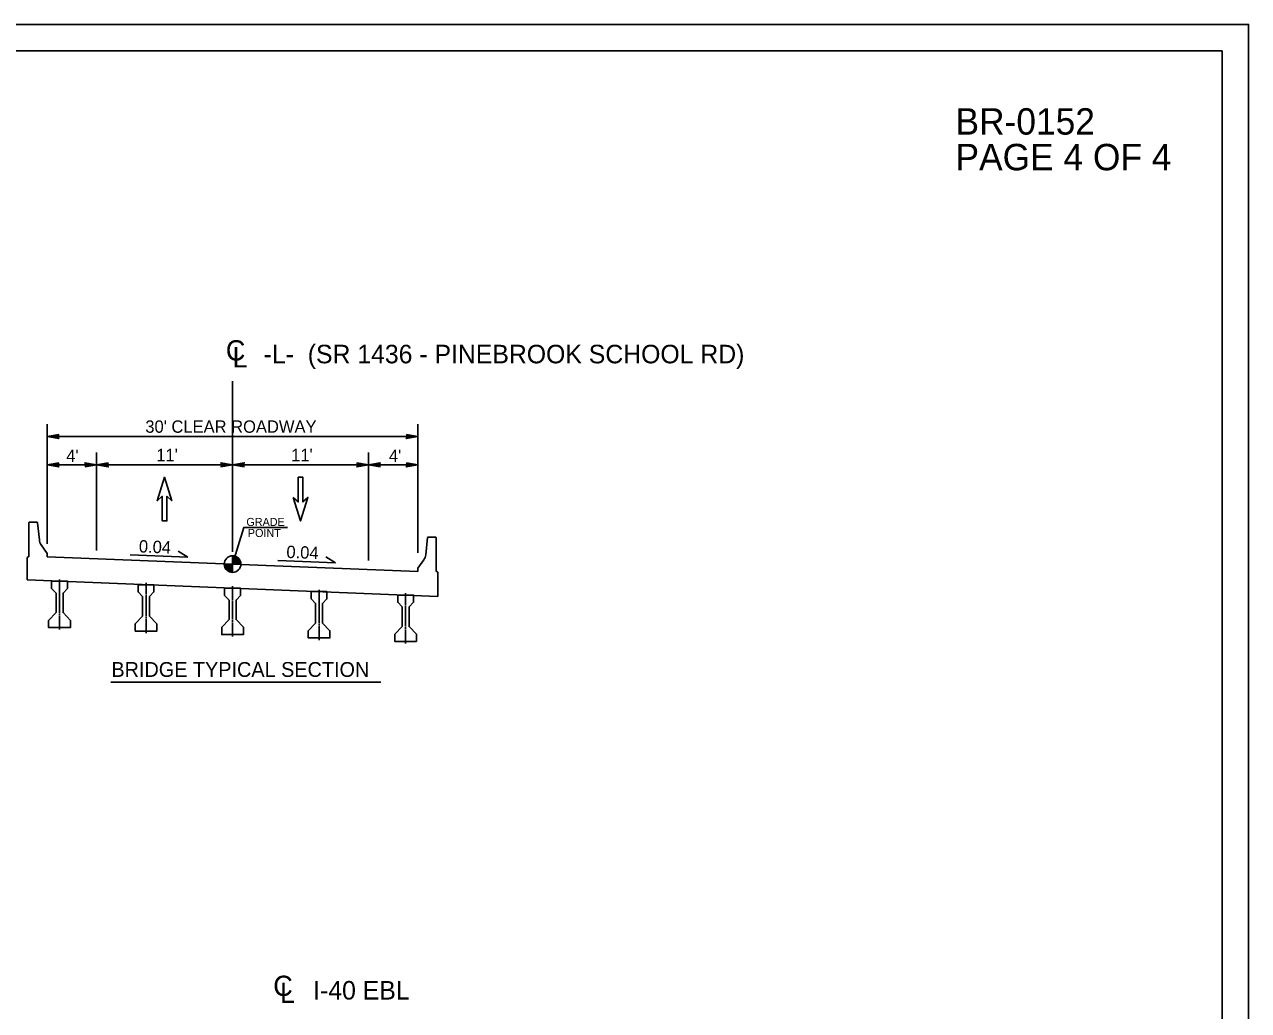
# Model space of a CAD drawing. Extents: x 1553195 to 1553792, y 810516 to 810787.
# Drawn here: x 1553567 to 1553666, y 810706.7 to 810786.5 of the extents above; entities that cross this region are included whole.
import ezdxf

# ---------------------------------------------------------------- set-up
doc = ezdxf.new("R2010")
doc.units = 0
for name, color, linetype in [('Old_Level_11', 7, 'Continuous'), ('Prop Dimension', 7, 'Continuous'), ('Prop Dimension Text', 7, 'Continuous'), ('Prop DSN Text', 7, 'Continuous'), ('Prop Pavement Schedule Description CELL', 7, 'Continuous'), ('Prop Shade Light', 7, 'Continuous'), ('Prop Terminator CELL', 7, 'Continuous'), ('Prop Typical Section', 7, 'Continuous'), ('Sheet Data Field CELL', 7, 'Continuous'), ('Sheet Plan CELL', 7, 'Continuous'), ('Typical Text ID Circle CELL', 7, 'Continuous'), ('z - Construction', 7, 'Continuous')]:
    doc.layers.add(name, color=color, linetype=linetype)

msp = doc.modelspace()

# ---------------------------------------------------------------- linework, layer by layer
at = {"layer": 'Old_Level_11'}
for p, q in [((1553583.839, 810742.867), (1553583.839, 810743.539)), ((1553583.168, 810742.867), (1553583.839, 810742.867)), ((1553583.838, 810742.196), (1553583.839, 810742.867)), ((1553583.839, 810742.867), (1553583.838, 810742.196)), ((1553584.511, 810742.867), (1553583.839, 810742.867))]:
    msp.add_line(p, q, dxfattribs=at)
for points in [[(1553583.845, 810743.539), (1553583.845, 810743.539), (1553583.845, 810742.867)], [(1553583.859, 810743.539), (1553583.859, 810742.867)], [(1553583.872, 810743.537), (1553583.872, 810742.867)], [(1553583.886, 810743.537), (1553583.886, 810742.867)], [(1553583.899, 810743.536), (1553583.899, 810742.867)], [(1553583.912, 810743.534), (1553583.912, 810742.867)], [(1553583.926, 810743.533), (1553583.926, 810742.867)], [(1553583.939, 810743.531), (1553583.939, 810742.867)], [(1553583.953, 810743.53), (1553583.953, 810742.867)], [(1553583.966, 810743.527), (1553583.966, 810742.867)], [(1553583.98, 810743.524), (1553583.98, 810742.867)], [(1553583.993, 810743.521), (1553583.993, 810742.867)], [(1553584.007, 810743.518), (1553584.007, 810742.867)], [(1553584.02, 810743.514), (1553584.02, 810742.867)], [(1553584.033, 810743.51), (1553584.033, 810742.867)], [(1553584.047, 810743.506), (1553584.047, 810742.867)], [(1553584.06, 810743.502), (1553584.06, 810742.867)], [(1553584.074, 810743.497), (1553584.074, 810742.867)], [(1553584.087, 810743.491), (1553584.087, 810742.867)], [(1553584.101, 810743.485), (1553584.101, 810742.867)], [(1553584.114, 810743.479), (1553584.114, 810742.867)], [(1553584.127, 810743.473), (1553584.127, 810742.867)], [(1553584.141, 810743.467), (1553584.141, 810742.867)], [(1553584.154, 810743.46), (1553584.154, 810742.867)], [(1553584.168, 810743.452), (1553584.168, 810742.867)], [(1553584.181, 810743.445), (1553584.181, 810742.867)], [(1553584.194, 810743.437), (1553584.194, 810742.867)], [(1553584.208, 810743.428), (1553584.208, 810742.867)], [(1553584.221, 810743.419), (1553584.221, 810742.867)], [(1553584.235, 810743.409), (1553584.235, 810742.867)], [(1553584.248, 810743.4), (1553584.248, 810742.867)], [(1553584.262, 810743.39), (1553584.262, 810742.867)], [(1553584.275, 810743.378), (1553584.275, 810742.867)], [(1553584.288, 810743.366), (1553584.288, 810742.867)], [(1553584.302, 810743.354), (1553584.302, 810742.867)], [(1553584.315, 810743.34), (1553584.315, 810742.867)], [(1553584.329, 810743.327), (1553584.329, 810742.867)], [(1553584.342, 810743.312), (1553584.342, 810742.867)], [(1553584.356, 810743.296), (1553584.356, 810742.867)], [(1553583.171, 810742.867), (1553583.171, 810742.794)], [(1553583.184, 810742.867), (1553583.184, 810742.715)], [(1553583.198, 810742.867), (1553583.198, 810742.668)], [(1553583.211, 810742.867), (1553583.211, 810742.627)], [(1553583.225, 810742.867), (1553583.225, 810742.596)], [(1553583.238, 810742.867), (1553583.238, 810742.568)], [(1553583.252, 810742.867), (1553583.252, 810742.542)], [(1553583.265, 810742.867), (1553583.265, 810742.518)], [(1553583.278, 810742.867), (1553583.278, 810742.498)], [(1553583.292, 810742.867), (1553583.292, 810742.478)], [(1553583.305, 810742.867), (1553583.305, 810742.46)], [(1553583.319, 810742.867), (1553583.319, 810742.444)], [(1553583.332, 810742.867), (1553583.332, 810742.427)], [(1553583.346, 810742.867), (1553583.346, 810742.412)], [(1553583.359, 810742.867), (1553583.359, 810742.398)], [(1553583.372, 810742.867), (1553583.372, 810742.384)], [(1553583.386, 810742.867), (1553583.386, 810742.372)], [(1553583.399, 810742.867), (1553583.399, 810742.36)], [(1553583.413, 810742.867), (1553583.413, 810742.348)], [(1553583.426, 810742.867), (1553583.426, 810742.338)], [(1553583.44, 810742.867), (1553583.44, 810742.327)], [(1553583.453, 810742.867), (1553583.453, 810742.318)], [(1553583.466, 810742.867), (1553583.466, 810742.309)], [(1553583.48, 810742.867), (1553583.48, 810742.301)], [(1553583.493, 810742.867), (1553583.493, 810742.292)], [(1553583.507, 810742.867), (1553583.507, 810742.284)], [(1553583.52, 810742.867), (1553583.52, 810742.277)], [(1553583.534, 810742.867), (1553583.534, 810742.269)], [(1553583.547, 810742.867), (1553583.547, 810742.263)], [(1553583.56, 810742.867), (1553583.56, 810742.257)], [(1553583.574, 810742.867), (1553583.574, 810742.251)], [(1553583.587, 810742.867), (1553583.587, 810742.245)], [(1553583.601, 810742.867), (1553583.601, 810742.239)], [(1553583.614, 810742.867), (1553583.614, 810742.235)], [(1553583.628, 810742.867), (1553583.628, 810742.23)], [(1553583.641, 810742.867), (1553583.641, 810742.226)], [(1553583.654, 810742.867), (1553583.654, 810742.223)], [(1553583.668, 810742.867), (1553583.668, 810742.218)], [(1553583.681, 810742.867), (1553583.681, 810742.216)], [(1553583.695, 810742.867), (1553583.695, 810742.212)], [(1553583.708, 810742.867), (1553583.708, 810742.21)], [(1553583.722, 810742.867), (1553583.722, 810742.207)], [(1553583.735, 810742.867), (1553583.735, 810742.205)], [(1553583.748, 810742.867), (1553583.748, 810742.202)], [(1553583.762, 810742.867), (1553583.762, 810742.201)], [(1553583.775, 810742.867), (1553583.775, 810742.199)], [(1553583.789, 810742.867), (1553583.789, 810742.198)], [(1553583.802, 810742.867), (1553583.802, 810742.198)], [(1553583.816, 810742.867), (1553583.816, 810742.196)], [(1553583.829, 810742.867), (1553583.829, 810742.196), (1553583.829, 810742.196)], [(1553584.369, 810743.279), (1553584.369, 810742.867)], [(1553584.383, 810743.261), (1553584.383, 810742.867)], [(1553584.396, 810743.242), (1553584.396, 810742.867)], [(1553584.409, 810743.221), (1553584.409, 810742.867)], [(1553584.423, 810743.199), (1553584.423, 810742.867)], [(1553584.436, 810743.175), (1553584.436, 810742.867)], [(1553584.45, 810743.146), (1553584.45, 810742.867)], [(1553584.463, 810743.115), (1553584.463, 810742.867)], [(1553584.476, 810743.078), (1553584.476, 810742.867)], [(1553584.49, 810743.032), (1553584.49, 810742.867)], [(1553584.503, 810742.963), (1553584.503, 810742.867)]]:
    msp.add_lwpolyline(points, dxfattribs=at)
msp.add_circle((1553583.839, 810742.868), 0.671, dxfattribs=at)
for start, end in [(359.99048, 89.99048), (179.99048, 269.99048)]:
    msp.add_arc((1553583.839, 810742.868), 0.671, start, end, dxfattribs=at)
at = {"layer": 'Prop Dimension'}
for p, q in [((1553580.217, 810743.418), (1553575.56, 810743.604)), ((1553580.217, 810743.418), (1553579.444, 810743.907)), ((1553592.155, 810742.968), (1553591.382, 810743.457)), ((1553592.155, 810742.968), (1553587.498, 810743.154))]:
    msp.add_line(p, q, dxfattribs=at)
at = {"layer": 'Prop Dimension Text'}
for p, q in [((1553568.839, 810743.468), (1553583.839, 810742.868)), ((1553567.231, 810742.946), (1553567.231, 810741.585)), ((1553583.839, 810742.868), (1553598.839, 810742.268)), ((1553567.231, 810741.585), (1553583.839, 810740.921)), ((1553569.839, 810741.631), (1553569.839, 810740.68)), ((1553576.839, 810741.351), (1553576.839, 810740.4)), ((1553600.446, 810741.746), (1553600.446, 810740.256)), ((1553569.839, 810740.647), (1553569.839, 810740.528)), ((1553569.839, 810740.492), (1553569.839, 810738.938)), ((1553576.839, 810740.367), (1553576.839, 810740.248)), ((1553583.839, 810741.071), (1553583.839, 810740.12)), ((1553583.839, 810740.921), (1553600.446, 810740.256)), ((1553590.839, 810740.791), (1553590.839, 810739.84)), ((1553597.839, 810740.511), (1553597.839, 810739.56)), ((1553576.839, 810740.212), (1553576.839, 810738.658)), ((1553583.839, 810740.087), (1553583.839, 810739.968)), ((1553583.839, 810739.932), (1553583.839, 810738.378)), ((1553590.839, 810739.807), (1553590.839, 810739.688)), ((1553590.839, 810739.652), (1553590.839, 810738.098)), ((1553597.839, 810739.527), (1553597.839, 810739.408)), ((1553597.839, 810739.372), (1553597.839, 810737.818)), ((1553569.839, 810738.881), (1553569.839, 810738.756)), ((1553569.839, 810738.702), (1553569.839, 810737.564)), ((1553576.839, 810738.601), (1553576.839, 810738.476)), ((1553576.839, 810738.422), (1553576.839, 810737.284)), ((1553583.839, 810738.321), (1553583.839, 810738.196)), ((1553583.839, 810738.142), (1553583.839, 810737.004)), ((1553590.839, 810738.041), (1553590.839, 810737.916)), ((1553590.839, 810737.862), (1553590.839, 810736.724)), ((1553597.839, 810737.761), (1553597.839, 810737.636)), ((1553597.839, 810737.582), (1553597.839, 810736.444))]:
    msp.add_line(p, q, dxfattribs=at)
for points in [[(1553570.479, 810741.481), (1553569.839, 810741.481), (1553569.199, 810741.481), (1553569.199, 810740.897), (1553569.559, 810740.522), (1553569.559, 810738.939), (1553568.959, 810738.314), (1553568.959, 810737.731), (1553569.839, 810737.731), (1553570.719, 810737.731), (1553570.719, 810738.314), (1553570.119, 810738.939), (1553570.119, 810740.522), (1553570.479, 810740.897), (1553570.479, 810741.481)], [(1553577.479, 810741.201), (1553576.839, 810741.201), (1553576.199, 810741.201), (1553576.199, 810740.617), (1553576.559, 810740.242), (1553576.559, 810738.659), (1553575.959, 810738.034), (1553575.959, 810737.451), (1553576.839, 810737.451), (1553577.719, 810737.451), (1553577.719, 810738.034), (1553577.119, 810738.659), (1553577.119, 810740.242), (1553577.479, 810740.617), (1553577.479, 810741.201)], [(1553584.479, 810740.921), (1553583.839, 810740.921), (1553583.199, 810740.921), (1553583.199, 810740.337), (1553583.559, 810739.962), (1553583.559, 810738.379), (1553582.959, 810737.754), (1553582.959, 810737.171), (1553583.839, 810737.171), (1553584.719, 810737.171), (1553584.719, 810737.754), (1553584.119, 810738.379), (1553584.119, 810739.962), (1553584.479, 810740.337), (1553584.479, 810740.921)], [(1553590.199, 810740.641), (1553590.839, 810740.641), (1553591.479, 810740.641), (1553591.479, 810740.057), (1553591.119, 810739.682), (1553591.119, 810738.099), (1553591.719, 810737.474), (1553591.719, 810736.891), (1553590.839, 810736.891), (1553589.959, 810736.891), (1553589.959, 810737.474), (1553590.559, 810738.099), (1553590.559, 810739.682), (1553590.199, 810740.057), (1553590.199, 810740.641)], [(1553597.199, 810740.361), (1553597.839, 810740.361), (1553598.479, 810740.361), (1553598.479, 810739.777), (1553598.119, 810739.402), (1553598.119, 810737.819), (1553598.719, 810737.194), (1553598.719, 810736.611), (1553597.839, 810736.611), (1553596.959, 810736.611), (1553596.959, 810737.194), (1553597.559, 810737.819), (1553597.559, 810739.402), (1553597.199, 810739.777), (1553597.199, 810740.361)]]:
    msp.add_lwpolyline(points, dxfattribs=at)
at = {"layer": 'Prop DSN Text'}
for points in [[(1553569.776, 810753.355), (1553568.839, 810753.194), (1553569.781, 810753.027), (1553569.661, 810753.194)], [(1553597.901, 810753.355), (1553598.839, 810753.194), (1553597.896, 810753.027), (1553598.016, 810753.194)], [(1553569.776, 810751.056), (1553568.839, 810750.894), (1553569.781, 810750.727), (1553569.661, 810750.894)], [(1553571.901, 810750.733), (1553572.839, 810750.894), (1553571.896, 810751.061), (1553572.016, 810750.894)], [(1553573.776, 810751.056), (1553572.839, 810750.894), (1553573.781, 810750.727), (1553573.661, 810750.894)], [(1553582.901, 810750.733), (1553583.839, 810750.894), (1553582.896, 810751.061), (1553583.016, 810750.894)], [(1553584.776, 810750.733), (1553583.839, 810750.894), (1553584.781, 810751.061), (1553584.661, 810750.894)], [(1553593.901, 810751.056), (1553594.839, 810750.894), (1553593.896, 810750.727), (1553594.016, 810750.894)], [(1553595.776, 810750.733), (1553594.839, 810750.894), (1553595.781, 810751.061), (1553595.661, 810750.894)], [(1553597.901, 810751.056), (1553598.839, 810750.894), (1553597.896, 810750.727), (1553598.016, 810750.894)]]:
    msp.add_lwpolyline(points, close=True, dxfattribs=at)
at = {"layer": 'Prop Pavement Schedule Description CELL'}
msp.add_line((1553573.978, 810733.316), (1553595.849, 810733.316), dxfattribs=at)
at = {"layer": 'Prop Terminator CELL'}
msp.add_lwpolyline([(1553663.906, 810631.126), (1553663.906, 810784.388), (1553424.506, 810784.388), (1553424.506, 810631.126)], close=True, dxfattribs=at)
at = {"layer": 'Prop Typical Section'}
msp.add_line((1553583.839, 810743.867), (1553583.839, 810757.677), dxfattribs=at)
for points in [[(1553578.932, 810747.988), (1553578.526, 810748.363), (1553578.526, 810746.363), (1553578.151, 810746.363), (1553578.151, 810748.363), (1553577.745, 810747.988), (1553578.339, 810749.894)], [(1553588.745, 810748.269), (1553589.151, 810747.894), (1553589.151, 810749.894), (1553589.526, 810749.894), (1553589.526, 810747.894), (1553589.932, 810748.269), (1553589.339, 810746.363)]]:
    msp.add_lwpolyline(points, close=True, dxfattribs=at)
at = {"layer": 'Sheet Data Field CELL'}
for p, q in [((1553567.394, 810746.248), (1553567.361, 810746.216)), ((1553567.361, 810746.216), (1553567.361, 810743.467)), ((1553568.024, 810746.248), (1553567.394, 810746.248)), ((1553568.06, 810746.212), (1553568.024, 810746.248)), ((1553568.207, 810744.821), (1553568.06, 810746.212)), ((1553568.839, 810743.728), (1553568.359, 810744.413)), ((1553599.47, 810743.621), (1553599.617, 810745.012)), ((1553599.617, 810745.012), (1553599.653, 810745.048)), ((1553599.653, 810745.048), (1553600.283, 810745.048)), ((1553600.283, 810745.048), (1553600.316, 810745.016)), ((1553600.316, 810745.016), (1553600.316, 810742.267)), ((1553567.296, 810743.467), (1553567.231, 810743.402)), ((1553567.231, 810743.402), (1553567.231, 810742.946)), ((1553567.361, 810743.467), (1553567.296, 810743.467)), ((1553568.839, 810743.468), (1553568.839, 810743.728)), ((1553598.839, 810742.528), (1553599.318, 810743.213)), ((1553598.839, 810742.268), (1553598.839, 810742.528)), ((1553600.316, 810742.267), (1553600.381, 810742.267)), ((1553600.381, 810742.267), (1553600.446, 810742.202)), ((1553600.446, 810742.202), (1553600.446, 810741.746))]:
    msp.add_line(p, q, dxfattribs=at)
for centre, start, end in [((1553569.071, 810744.912), 186.01107, 214.9913), ((1553598.606, 810743.712), 325.0087, 353.98893)]:
    msp.add_arc(centre, 0.869, start, end, dxfattribs=at)
at = {"layer": 'Sheet Plan CELL'}
msp.add_lwpolyline([(1553666.043, 810628.988), (1553666.043, 810786.526), (1553422.368, 810786.526), (1553422.368, 810628.988)], close=True, dxfattribs=at)
at = {"layer": 'Typical Text ID Circle CELL'}
msp.add_lwpolyline([(1553583.839, 810742.868), (1553584.742, 810745.821), (1553588.28, 810745.821)], dxfattribs=at)
at = {"layer": 'z - Construction'}
for p, q in [((1553568.839, 810744.52), (1553568.839, 810754.194)), ((1553598.839, 810743.778), (1553598.839, 810754.194)), ((1553568.839, 810753.194), (1553598.839, 810753.194)), ((1553572.839, 810743.961), (1553572.839, 810751.894)), ((1553594.839, 810743.148), (1553594.839, 810751.894)), ((1553572.839, 810750.894), (1553568.839, 810750.894)), ((1553583.839, 810750.894), (1553572.839, 810750.894)), ((1553583.839, 810750.894), (1553594.839, 810750.894)), ((1553594.839, 810750.894), (1553598.839, 810750.894))]:
    msp.add_line(p, q, dxfattribs=at)

# ---------------------------------------------------------------- texts
at = {"layer": 'Prop Pavement Schedule Description CELL'}
for s, height, p in [('BR-0152', 2.1375, (1553642.335, 810777.614)), ('PAGE 4 OF 4', 2.1375, (1553642.335, 810774.729)), ('-L-  (SR 1436 - PINEBROOK SCHOOL RD)', 1.5, (1553586.355, 810759.112)), ("30' CLEAR ROADWAY", 1, (1553576.78, 810753.494)), ("11'", 1, (1553577.664, 810751.194)), ("11'", 1, (1553588.58, 810751.194)), ("4'", 1, (1553570.385, 810751.135)), ("4'", 1, (1553596.491, 810751.135)), ('BRIDGE TYPICAL SECTION', 1.2, (1553574.035, 810733.742)), ('I-40 EBL', 1.5, (1553590.361, 810707.637))]:
    msp.add_text(s, height=height, dxfattribs=at).set_placement(p)
for p in [(1553576.242, 810743.819), (1553588.18, 810743.369)]:
    msp.add_text('0.04', height=1, rotation=357.70939, dxfattribs=at).set_placement(p)
at = {"layer": 'Prop Shade Light'}
for p in [(1553583.293, 810759.341), (1553587.128, 810707.928)]:
    msp.add_text('C', height=1.64, dxfattribs=at).set_placement(p)
for p in [(1553583.838, 810758.781), (1553587.673, 810707.368)]:
    msp.add_text('L', height=1.641, rotation=359.9469, dxfattribs=at).set_placement(p)
at = {"layer": 'Typical Text ID Circle CELL'}
for s, p in [('GRADE', (1553584.958, 810745.951)), ('POINT', (1553585.078, 810745.059))]:
    msp.add_text(s, height=0.6525, dxfattribs=at).set_placement(p)

doc.saveas('drawing.dxf')
